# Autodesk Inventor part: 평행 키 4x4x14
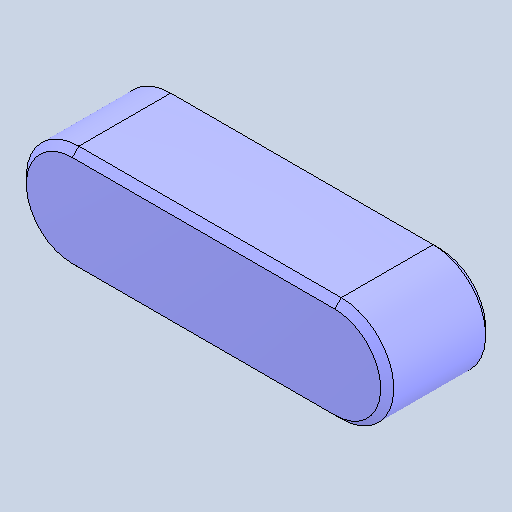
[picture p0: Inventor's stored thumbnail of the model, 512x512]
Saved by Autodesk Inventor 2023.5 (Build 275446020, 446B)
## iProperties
Created: 2026-07
Part Number: 평행 키 4x4x14
Material: 강철, 연강
Document SubType Name: Modeling
Designer: mirae
Density: 7.86 g/cm^3
Appearance: 기본값
Author: jhkim
Revision Number: 1
Sending System: Autodesk Inventor 2027
Preprocessor: ST-DEVELOPER v20.1
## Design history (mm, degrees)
node "평행 키 4x4x141"
node "솔리드2"
node "솔리드1"
